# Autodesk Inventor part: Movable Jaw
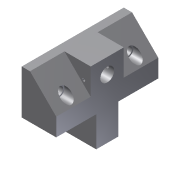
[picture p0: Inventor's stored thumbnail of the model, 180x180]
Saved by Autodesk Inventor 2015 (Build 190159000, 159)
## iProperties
Shininess: 77.0
Length Units: 11269
Angle Units: 11279
Time Units: 11290
Mass Units: 11283
Length Display Precision: 3
Angle Display Precision: 2
Created: 2002-02
Part Number: Movable Jaw
Document SubType Name: Modeling
Designer: ***
Density: 1 g/cm^3
Material: Generic
Appearance: Default
Density: 0.0
Volumn: 0.0
Area: 0.0
PropertySet Name: Model Information
Control State: 0
Master: False
Checked Out: False
Author: ***
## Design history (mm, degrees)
sketch "Sketch2"
  geometry: L1 (2.39, 41.509)-(2.39, 9.509); L2 (2.39, 9.509)-(-22.61, 9.509); L3 (-22.61, 9.509)-(-22.61, 22.509); L4 (-22.61, 22.509)-(-3.61, 41.509); L5 (-3.61, 41.509)-(2.39, 41.509)
  constraints: 10 end point, 2 parallel, 1 perpendicular, 1 vertical
  dimensions: "d0" = 25 distance of L1.end L2.end; "d2" = 13 distance of L2.end L3.end; "d3" = 32 distance between parallel lines of L5 L2; "d4" = 6 distance of L4.end L1.start
extrude "Extrusion1" new body sketch "Sketch2" stored distance "d5" = 74; taper "d6" = 0 deg
sketch "Sketch3"
  geometry: L1 (-19, 25)-(11, 25); L2 (11, 25)-(11, 49); L3 (11, 49)-(-19, 49); L4 (-19, 49)-(-19, 25); L5 (0, 0)-(13, 0) reference; L6 (-19, 74)-(-19, 0) reference; L7 (11.924, 29)-(35, 29); L8 (35, 29)-(35, 45); L9 (35, 45)-(11.924, 45); L10 (11.924, 45)-(11.924, 29); L11 (13, 74)-(13, 0) reference
  constraints: 16 end point, 4 parallel, 2 horizontal, 2 perpendicular, 1 collinear
  dimensions: "d7" = 24 distance of L3.end L1.start; "d8" = 30 distance of L1.start L1.end; "d9" = 25 distance between parallel lines of L5 L1; "d10" = 16 distance of L7.end L8.end; "d11" = 4 distance between parallel lines of L3 L9; "d12" = 22 distance between parallel lines of L11 L8
extrude "Extrusion2" join sketch "Sketch3" distance "d13" = 25; taper "d14" = 0 deg
sketch "Sketch4"
  geometry: L1 (-19, -25)-(-19, -49) reference; L2 (-19, -49)-(0, -49) reference; 1 further point
  dimensions: "d15" = 11 distance from line of L1 point (-8, -37); "d16" = 12 distance from line of L2 point (-8, -37)
hole "Hole1" sketch "Sketch4" at (-8, -37) diameter "d17" = 10; stored, may be unused: countersink angle "d21" = 82 deg, drill point angle "d23" = 0 deg; dims "d18" = 6, "d19" = 4, "d20" = 2, "d22" = 13
sketch "Sketch5"
  geometry: L1 (-19, -49)-(-19, -74) reference; L2 (0, -74)-(13, -74) reference; 1 further point
  dimensions: "d24" = 14 distance from line of L1 point (-5, -62); "d25" = 12 distance from line of L2 point (-5, -62)
hole "Hole2" sketch "Sketch5" at (-5, -62) diameter "d26" = 6; stored, may be unused: countersink angle "d30" = 82 deg, drill point angle "d32" = 0 deg; dims "d27" = 6, "d28" = 8, "d29" = 10, "d31" = 13
mirror "Mirror1"
sketch "Sketch6"
  geometry: L1 (0, 19)-(0, 0) reference; 1 further point
  dimensions: "d33" = 5 distance from line of L1 point (-5, 8); "d34" = 11 vertical distance of L1.start point (-5, 8)
hole "Hole3" sketch "Sketch6" at (-5, 8) diameter "d35" = 2; stored, may be unused: countersink angle "d39" = 82 deg, drill point angle "d41" = 0 deg; dims "d36" = 6, "d37" = 8, "d38" = 10, "d40" = 13
body "Solid1"
